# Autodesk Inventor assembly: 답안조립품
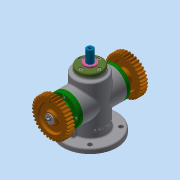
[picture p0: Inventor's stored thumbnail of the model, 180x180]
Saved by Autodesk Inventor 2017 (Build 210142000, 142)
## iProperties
Part Number: 답안조립품
Material: 일반
Document SubType Name: Assembly
Designer: mrc
Mass: 1857.26 g
Surface Area: 1725.08 cm^2
Volume: 520.44 cm^3
Density: 3.56862 g/cm^3
Author: mrc
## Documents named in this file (17)
- C:\Users\mrc\Desktop\600606V1008\답안조립품.iam
- C:\Users\mrc\Desktop\600606V1008\본체.ipt
- C:\Users\mrc\Desktop\600606V1008\가변스프링.ipt
- C:\Users\mrc\Desktop\600606V1008\멈춤링.ipt
- C:\Users\mrc\Desktop\600606V1008\베어링 6203.ipt
- C:\Users\mrc\Desktop\600606V1008\볼트 M4.ipt
- C:\Users\mrc\Desktop\600606V1008\부시.ipt
- C:\Users\mrc\Desktop\600606V1008\스퍼기어.ipt
- C:\Users\mrc\Desktop\600606V1008\스프링와셔.ipt
- C:\Users\mrc\Desktop\600606V1008\스프링조립용 와셔.ipt
- C:\Users\mrc\Desktop\600606V1008\슬라이더.ipt
- C:\Users\mrc\Desktop\600606V1008\오일 실 17 30 8.ipt
- C:\Users\mrc\Desktop\600606V1008\커버 A.ipt
- C:\Users\mrc\Desktop\600606V1008\커버 B.ipt
- C:\Users\mrc\Desktop\600606V1008\키 4x4x12.ipt
- C:\Users\mrc\Desktop\600606V1008\편심축.ipt
- C:\Users\mrc\Desktop\600606V1008\평와셔.ipt
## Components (1 placed, 1 different names)
1. 가변스프링:1
